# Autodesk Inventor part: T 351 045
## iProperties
Company: Mayer & Müller AG Schaltgeräte
Created: 2006-10
Part Number: T 351 045
Material: Ag - W75
Document SubType Name: Modeling
Designer: I.Baliuc
Manufacturer: Standard
Standards Organization: Custom
Description: Edelmetalplatte
Density: 10.49 g/cm^3
Zweck: Vork. bewegl. 340054
Author: T.Messerschmitt
Revision Number: 351045
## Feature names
1. Extrusion2
